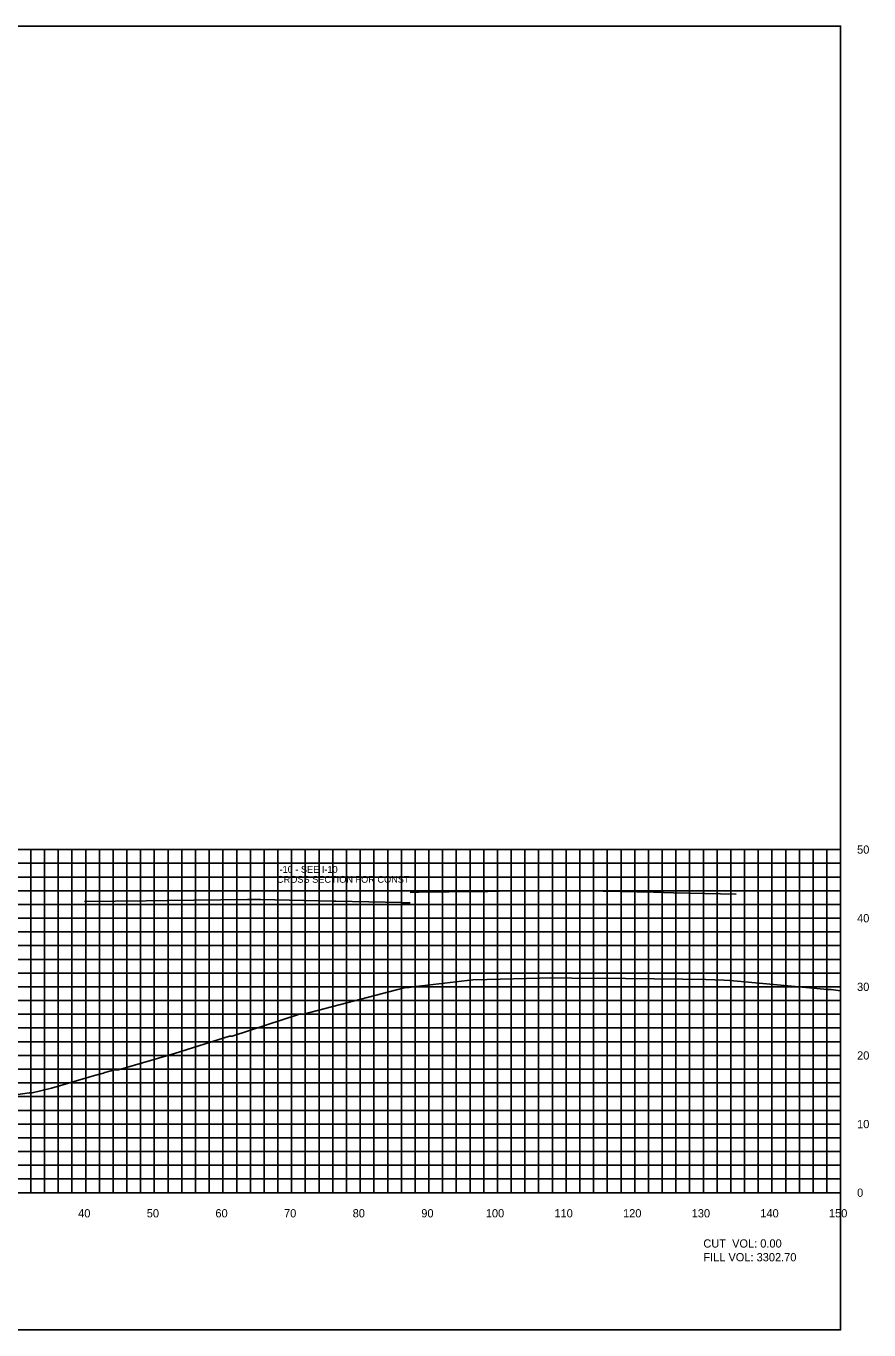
# Model space of a CAD drawing. Extents: x 1797714 to 1804825, y 249015 to 250269.
# Drawn here: x 1804702.3 to 1804825.1, y 250079.4 to 250269.4 of the extents above; entities that cross this region are included whole.
import ezdxf

# ---------------------------------------------------------------- set-up
doc = ezdxf.new("R2010")
doc.units = 0
for name, color, linetype in [('10', 7, 'Continuous'), ('3', 7, 'Continuous'), ('31', 7, 'Continuous'), ('60', 7, 'Continuous'), ('ANNO-TXT', 7, 'Continuous'), ('CL-CNST', 7, 'Continuous'), ('Level 62', 7, 'Continuous'), ('M-ROADS', 7, 'Continuous')]:
    doc.layers.add(name, color=color, linetype=linetype)

msp = doc.modelspace()

# ---------------------------------------------------------------- linework, layer by layer
msp.add_lwpolyline([(1804521, 250079.43), (1804821, 250079.43), (1804821, 250269.43), (1804521, 250269.43)], close=True)
at = {"layer": '60'}
for p, q in [((1804821, 250099.43), (1804821, 250149.43)), ((1804821.06, 250149.43), (1804821, 250149.43)), ((1804821.06, 250139.43), (1804821, 250139.43)), ((1804821.06, 250129.43), (1804821, 250129.43)), ((1804821.06, 250119.43), (1804821, 250119.43)), ((1804821.06, 250109.43), (1804821, 250109.43)), ((1804521, 250099.43), (1804821, 250099.43)), ((1804711, 250099.37), (1804711, 250099.43)), ((1804721, 250099.37), (1804721, 250099.43)), ((1804731, 250099.37), (1804731, 250099.43)), ((1804741, 250099.37), (1804741, 250099.43)), ((1804751, 250099.37), (1804751, 250099.43)), ((1804761, 250099.37), (1804761, 250099.43)), ((1804771, 250099.37), (1804771, 250099.43)), ((1804781, 250099.37), (1804781, 250099.43)), ((1804791, 250099.37), (1804791, 250099.43)), ((1804801, 250099.37), (1804801, 250099.43)), ((1804811, 250099.37), (1804811, 250099.43)), ((1804821, 250099.37), (1804821, 250099.43)), ((1804821.06, 250099.43), (1804821, 250099.43))]:
    msp.add_line(p, q, dxfattribs=at)
at = {"layer": 'CL-CNST'}
for points in [[(1804758.3, 250143.18), (1804759.44, 250143.2), (1804759.55, 250143.2), (1804768.32, 250143.3), (1804769.6, 250143.32), (1804771.29, 250143.35), (1804781.66, 250143.47), (1804783.96, 250143.42), (1804793.73, 250143.2), (1804796.64, 250143.14), (1804805.79, 250142.93)], [(1804710.81, 250141.87), (1804719.8, 250141.98), (1804722.87, 250142.02), (1804734.58, 250142.17), (1804734.93, 250142.17), (1804736.49, 250142.14), (1804746.99, 250141.91), (1804747.43, 250141.9), (1804757.04, 250141.7), (1804757.14, 250141.69), (1804758.29, 250141.67)]]:
    msp.add_lwpolyline(points, dxfattribs=at)
at = {"layer": 'Level 62'}
for p, q in [((1804521, 250149.43), (1804821, 250149.43)), ((1804521, 250149.43), (1804821, 250149.43)), ((1804703, 250099.43), (1804703, 250149.43)), ((1804703, 250099.43), (1804703, 250149.43)), ((1804705, 250099.43), (1804705, 250149.43)), ((1804705, 250099.43), (1804705, 250149.43)), ((1804707, 250099.43), (1804707, 250149.43)), ((1804707, 250099.43), (1804707, 250149.43)), ((1804709, 250099.43), (1804709, 250149.43)), ((1804709, 250099.43), (1804709, 250149.43)), ((1804711, 250099.43), (1804711, 250149.43)), ((1804711, 250099.43), (1804711, 250149.43)), ((1804713, 250099.43), (1804713, 250149.43)), ((1804713, 250099.43), (1804713, 250149.43)), ((1804715, 250099.43), (1804715, 250149.43)), ((1804715, 250099.43), (1804715, 250149.43)), ((1804717, 250099.43), (1804717, 250149.43)), ((1804717, 250099.43), (1804717, 250149.43)), ((1804719, 250099.43), (1804719, 250149.43)), ((1804719, 250099.43), (1804719, 250149.43)), ((1804721, 250099.43), (1804721, 250149.43)), ((1804721, 250099.43), (1804721, 250149.43)), ((1804723, 250099.43), (1804723, 250149.43)), ((1804723, 250099.43), (1804723, 250149.43)), ((1804725, 250099.43), (1804725, 250149.43)), ((1804725, 250099.43), (1804725, 250149.43)), ((1804727, 250099.43), (1804727, 250149.43)), ((1804727, 250099.43), (1804727, 250149.43)), ((1804729, 250099.43), (1804729, 250149.43)), ((1804729, 250099.43), (1804729, 250149.43)), ((1804731, 250099.43), (1804731, 250149.43)), ((1804731, 250099.43), (1804731, 250149.43)), ((1804733, 250099.43), (1804733, 250149.43)), ((1804733, 250099.43), (1804733, 250149.43)), ((1804735, 250099.43), (1804735, 250149.43)), ((1804735, 250099.43), (1804735, 250149.43)), ((1804737, 250099.43), (1804737, 250149.43)), ((1804737, 250099.43), (1804737, 250149.43)), ((1804739, 250099.43), (1804739, 250149.43)), ((1804739, 250099.43), (1804739, 250149.43)), ((1804741, 250099.43), (1804741, 250149.43)), ((1804741, 250099.43), (1804741, 250149.43)), ((1804743, 250099.43), (1804743, 250149.43)), ((1804743, 250099.43), (1804743, 250149.43)), ((1804745, 250099.43), (1804745, 250149.43)), ((1804745, 250099.43), (1804745, 250149.43)), ((1804747, 250099.43), (1804747, 250149.43)), ((1804747, 250099.43), (1804747, 250149.43)), ((1804749, 250099.43), (1804749, 250149.43)), ((1804749, 250099.43), (1804749, 250149.43)), ((1804751, 250099.43), (1804751, 250149.43)), ((1804751, 250099.43), (1804751, 250149.43)), ((1804753, 250099.43), (1804753, 250149.43)), ((1804753, 250099.43), (1804753, 250149.43)), ((1804755, 250099.43), (1804755, 250149.43)), ((1804755, 250099.43), (1804755, 250149.43)), ((1804757, 250099.43), (1804757, 250149.43)), ((1804757, 250099.43), (1804757, 250149.43)), ((1804759, 250099.43), (1804759, 250149.43)), ((1804759, 250099.43), (1804759, 250149.43)), ((1804761, 250099.43), (1804761, 250149.43)), ((1804761, 250099.43), (1804761, 250149.43)), ((1804763, 250099.43), (1804763, 250149.43)), ((1804763, 250099.43), (1804763, 250149.43)), ((1804765, 250099.43), (1804765, 250149.43)), ((1804765, 250099.43), (1804765, 250149.43)), ((1804767, 250099.43), (1804767, 250149.43)), ((1804767, 250099.43), (1804767, 250149.43)), ((1804769, 250099.43), (1804769, 250149.43)), ((1804769, 250099.43), (1804769, 250149.43)), ((1804771, 250099.43), (1804771, 250149.43)), ((1804771, 250099.43), (1804771, 250149.43)), ((1804773, 250099.43), (1804773, 250149.43)), ((1804773, 250099.43), (1804773, 250149.43)), ((1804775, 250099.43), (1804775, 250149.43)), ((1804775, 250099.43), (1804775, 250149.43)), ((1804777, 250099.43), (1804777, 250149.43)), ((1804777, 250099.43), (1804777, 250149.43)), ((1804779, 250099.43), (1804779, 250149.43)), ((1804779, 250099.43), (1804779, 250149.43)), ((1804781, 250099.43), (1804781, 250149.43)), ((1804781, 250099.43), (1804781, 250149.43)), ((1804783, 250099.43), (1804783, 250149.43)), ((1804783, 250099.43), (1804783, 250149.43)), ((1804785, 250099.43), (1804785, 250149.43)), ((1804785, 250099.43), (1804785, 250149.43)), ((1804787, 250099.43), (1804787, 250149.43)), ((1804787, 250099.43), (1804787, 250149.43)), ((1804789, 250099.43), (1804789, 250149.43)), ((1804789, 250099.43), (1804789, 250149.43)), ((1804791, 250099.43), (1804791, 250149.43)), ((1804791, 250099.43), (1804791, 250149.43)), ((1804793, 250099.43), (1804793, 250149.43)), ((1804793, 250099.43), (1804793, 250149.43)), ((1804795, 250099.43), (1804795, 250149.43)), ((1804795, 250099.43), (1804795, 250149.43)), ((1804797, 250099.43), (1804797, 250149.43)), ((1804797, 250099.43), (1804797, 250149.43)), ((1804799, 250099.43), (1804799, 250149.43)), ((1804799, 250099.43), (1804799, 250149.43)), ((1804801, 250099.43), (1804801, 250149.43)), ((1804801, 250099.43), (1804801, 250149.43)), ((1804803, 250099.43), (1804803, 250149.43)), ((1804803, 250099.43), (1804803, 250149.43)), ((1804805, 250099.43), (1804805, 250149.43)), ((1804805, 250099.43), (1804805, 250149.43)), ((1804807, 250099.43), (1804807, 250149.43)), ((1804807, 250099.43), (1804807, 250149.43)), ((1804809, 250099.43), (1804809, 250149.43)), ((1804809, 250099.43), (1804809, 250149.43)), ((1804811, 250099.43), (1804811, 250149.43)), ((1804811, 250099.43), (1804811, 250149.43)), ((1804813, 250099.43), (1804813, 250149.43)), ((1804813, 250099.43), (1804813, 250149.43)), ((1804815, 250099.43), (1804815, 250149.43)), ((1804815, 250099.43), (1804815, 250149.43)), ((1804817, 250099.43), (1804817, 250149.43)), ((1804817, 250099.43), (1804817, 250149.43)), ((1804819, 250099.43), (1804819, 250149.43)), ((1804819, 250099.43), (1804819, 250149.43)), ((1804821, 250099.43), (1804821, 250149.43)), ((1804821, 250099.43), (1804821, 250149.43)), ((1804521, 250147.43), (1804821, 250147.43)), ((1804521, 250147.43), (1804821, 250147.43)), ((1804521, 250145.43), (1804821, 250145.43)), ((1804521, 250145.43), (1804821, 250145.43)), ((1804521, 250143.43), (1804821, 250143.43)), ((1804521, 250143.43), (1804821, 250143.43)), ((1804521, 250141.43), (1804821, 250141.43)), ((1804521, 250141.43), (1804821, 250141.43)), ((1804521, 250139.43), (1804821, 250139.43)), ((1804521, 250139.43), (1804821, 250139.43)), ((1804521, 250137.43), (1804821, 250137.43)), ((1804521, 250137.43), (1804821, 250137.43)), ((1804521, 250135.43), (1804821, 250135.43)), ((1804521, 250135.43), (1804821, 250135.43)), ((1804521, 250133.43), (1804821, 250133.43)), ((1804521, 250133.43), (1804821, 250133.43)), ((1804521, 250131.43), (1804821, 250131.43)), ((1804521, 250131.43), (1804821, 250131.43)), ((1804521, 250129.43), (1804821, 250129.43)), ((1804521, 250129.43), (1804821, 250129.43)), ((1804521, 250127.43), (1804821, 250127.43)), ((1804521, 250127.43), (1804821, 250127.43)), ((1804521, 250125.43), (1804821, 250125.43)), ((1804521, 250125.43), (1804821, 250125.43)), ((1804521, 250123.43), (1804821, 250123.43)), ((1804521, 250123.43), (1804821, 250123.43)), ((1804521, 250121.43), (1804821, 250121.43)), ((1804521, 250121.43), (1804821, 250121.43)), ((1804521, 250119.43), (1804821, 250119.43)), ((1804521, 250119.43), (1804821, 250119.43)), ((1804521, 250117.43), (1804821, 250117.43)), ((1804521, 250117.43), (1804821, 250117.43)), ((1804521, 250115.43), (1804821, 250115.43)), ((1804521, 250115.43), (1804821, 250115.43)), ((1804521, 250113.43), (1804821, 250113.43)), ((1804521, 250113.43), (1804821, 250113.43)), ((1804521, 250111.43), (1804821, 250111.43)), ((1804521, 250111.43), (1804821, 250111.43)), ((1804521, 250109.43), (1804821, 250109.43)), ((1804521, 250109.43), (1804821, 250109.43)), ((1804521, 250107.43), (1804821, 250107.43)), ((1804521, 250107.43), (1804821, 250107.43)), ((1804521, 250105.43), (1804821, 250105.43)), ((1804521, 250105.43), (1804821, 250105.43)), ((1804521, 250103.43), (1804821, 250103.43)), ((1804521, 250103.43), (1804821, 250103.43)), ((1804521, 250101.43), (1804821, 250101.43)), ((1804521, 250101.43), (1804821, 250101.43)), ((1804521, 250099.43), (1804821, 250099.43)), ((1804521, 250099.43), (1804821, 250099.43))]:
    msp.add_line(p, q, dxfattribs=at)
at = {"layer": 'M-ROADS'}
msp.add_lwpolyline([(1804700.84, 250113.67), (1804702.75, 250113.97), (1804703.19, 250113.98), (1804706.01, 250114.68), (1804712.3, 250116.52), (1804713.58, 250116.87), (1804713.8, 250116.93), (1804715.24, 250117.34), (1804715.73, 250117.34), (1804715.76, 250117.34), (1804723.95, 250119.69), (1804731.94, 250122.23), (1804732.33, 250122.26), (1804742.28, 250125.47), (1804742.54, 250125.46), (1804742.72, 250125.45), (1804757.42, 250129.29), (1804758.05, 250129.33), (1804758.27, 250129.37), (1804758.28, 250129.37), (1804758.31, 250129.38), (1804758.35, 250129.38), (1804758.44, 250129.39), (1804758.76, 250129.43), (1804760.79, 250129.66), (1804767.4, 250130.44), (1804769.45, 250130.49), (1804777.15, 250130.68), (1804778.69, 250130.72), (1804781.85, 250130.69), (1804789.65, 250130.62), (1804797.99, 250130.54), (1804801.36, 250130.5), (1804804, 250130.38), (1804804.87, 250130.34), (1804806.53, 250130.19), (1804819.1, 250129.05), (1804819.35, 250129.05), (1804819.62, 250129.05), (1804821, 250128.86)], dxfattribs=at)

# ---------------------------------------------------------------- texts
at = {"layer": '10'}
for s, p in [('40', (1804709.9, 250095.83)), ('50', (1804719.9, 250095.83)), ('60', (1804729.9, 250095.83)), ('70', (1804739.9, 250095.83)), ('80', (1804749.9, 250095.83)), ('90', (1804759.9, 250095.83)), ('100', (1804769.3, 250095.83)), ('110', (1804779.3, 250095.83)), ('120', (1804789.3, 250095.83)), ('130', (1804799.3, 250095.83)), ('140', (1804809.3, 250095.83)), ('150', (1804819.3, 250095.83))]:
    msp.add_text(s, height=1.2, dxfattribs=at).set_placement(p)
at = {"layer": '3'}
for s, p in [('I-10 - SEE I-10 ', (1804738.87, 250146.04)), ('CROSS SECTION FOR CONST ', (1804738.87, 250144.59))]:
    msp.add_text(s, height=1, dxfattribs=at).set_placement(p)
at = {"layer": '31'}
for s, p in [('50', (1804823.4, 250148.83)), ('40', (1804823.4, 250138.83)), ('30', (1804823.4, 250128.83)), ('20', (1804823.4, 250118.83)), ('10', (1804823.4, 250108.83)), ('0', (1804823.4, 250098.83))]:
    msp.add_text(s, height=1.2, dxfattribs=at).set_placement(p)
at = {"layer": 'ANNO-TXT'}
for s, p in [('CUT  VOL: 0.00', (1804801, 250091.43)), ('FILL VOL: 3302.70', (1804801, 250089.43))]:
    msp.add_text(s, height=1.2, dxfattribs=at).set_placement(p)

doc.saveas('drawing.dxf')
